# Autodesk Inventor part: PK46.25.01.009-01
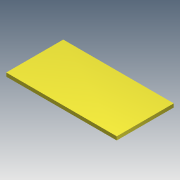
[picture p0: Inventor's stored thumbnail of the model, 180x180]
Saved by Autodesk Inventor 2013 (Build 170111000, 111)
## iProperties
Created: 2005-04
Part Number: PK46.25.01.009-01
Material: Steel, Mild
Document SubType Name: Modeling
Designer: salex
Manufacturer: Standard
Standards Organization: Custom
Density: 7.86 g/cm^3
Mass: 3898.56 g
Surface Area: 1086 cm^2
Volume: 496 cm^3
Author: salex
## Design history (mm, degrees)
sketch "Эскиз1"
  geometry: L1 (0, 0)-(310, 0); L2 (310, 0)-(310, 160); L3 (310, 160)-(0, 160); L4 (0, 160)-(0, 0)
  constraints: 8 end point, 2 parallel, 1 horizontal, 1 perpendicular, 1 other
  dimensions: "d0" = 310 distance of L1.start L1.end; "d1" = 160 distance of L3.end L1.start
extrude "Выдавливание1" new body sketch "Эскиз1" distance "d2" = 10; taper "d3" = 0 deg
body "Solid1"
